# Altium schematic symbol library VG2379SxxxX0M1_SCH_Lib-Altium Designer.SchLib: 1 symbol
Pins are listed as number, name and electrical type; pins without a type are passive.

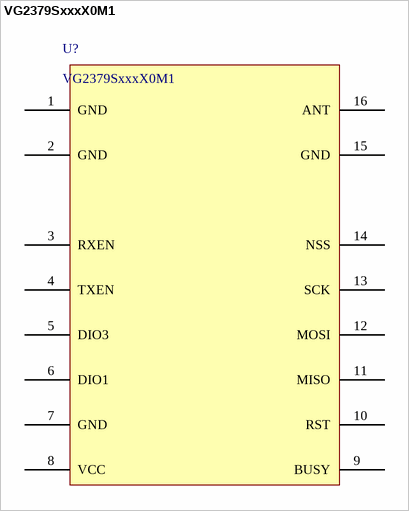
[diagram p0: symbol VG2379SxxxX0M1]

## VG2379SxxxX0M1
designator U?
pins: 1 GND, 2 GND, 3 RXEN, 4 TXEN, 5 DIO3, 6 DIO1, 7 GND, 8 VCC, 9 BUSY, 10 RST, 11 MISO, 12 MOSI, 13 SCK, 14 NSS, 15 GND, 16 ANT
